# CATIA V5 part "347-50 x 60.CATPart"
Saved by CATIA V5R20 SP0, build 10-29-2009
Part number: 347-50 x 60
Definition: NONE
Nomenclature: 347-50 x 60
Source: Unknown
Description: 347-50 x 60
Bounding box of the stored display mesh (mm): x 0 to 60, y -35 to 35, z -35 to 35
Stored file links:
  C:\Users\Utente\Desktop\IO LAVORO\3D X SITO CF\X SITO\3D files 347\347-50 x 60.CATPart
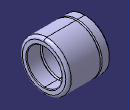
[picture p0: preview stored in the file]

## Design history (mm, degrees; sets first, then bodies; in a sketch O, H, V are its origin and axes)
Body1 "347-50 x 60" (main body)
  Solid1: solid without history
